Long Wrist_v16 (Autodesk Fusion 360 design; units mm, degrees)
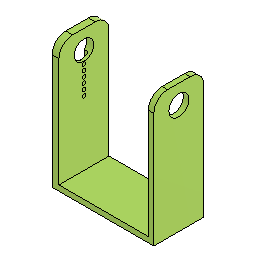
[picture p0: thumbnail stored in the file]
parameter "d10" = 7 (= "( 7 / 2 ) * 1 mm + 1.5 mm + 2 mm")
sketch "Sketch1" plane through (0, 0, 0) normal (0, 0, 1) x axis (1, 0, 0)
  line L1 (-18.6, -9.15) -> (18.6, -9.15)
  line L2 (-18.6, 9.15) -> (-18.6, -9.15)
  line L3 (18.6, 9.15) -> (-18.6, 9.15)
  line L4 (18.6, -9.15) -> (18.6, 9.15)
  line L5 (-18.6, 9.15) -> (18.6, -9.15)
  line L6 (18.6, 9.15) -> (-18.6, -9.15)
  line L7 (16.6, 9.15) -> (18.6, 9.15)
  line L8 (16.6, -9.15) -> (16.6, 9.15)
  line L9 (18.6, -9.15) -> (16.6, -9.15)
  line L10 (18.6, 9.15) -> (18.6, -9.15)
  line L11 (-16.1, 9.15) -> (-18.6, 9.15)
  line L12 (-16.1, -9.15) -> (-16.1, 9.15)
  line L13 (-18.6, -9.15) -> (-16.1, -9.15)
  line L14 (-18.6, 9.15) -> (-18.6, -9.15)
  point P6 (0, 0)
  point P1 (0, 0)
  point P4 (-18.6, 9.15)
  point P5 (18.6, 9.15)
  point P3 (-18.6, -9.15)
  point P7 (16.6, 9.15)
  point P10 (-16.1, 9.15)
  point P11 (-16.1, -9.15)
  point P8 (16.6, -9.15)
  horizontal L1
  perpendicular L1 L2
  parallel L1 L3
  parallel L2 L4
  coincident L5 P6
  coincident L6 P6
  coincident P1 P6
  horizontal L7
  vertical L8
  horizontal L9
  vertical L10
  horizontal L11
  vertical L12
  horizontal L13
  vertical L14
  dimension "d1" distance P4 P5 = 37.2 (= "35.5 mm + 2 mm - 0.3 mm")
  dimension "d2" distance P3 P4 = 18.3
  dimension "d3" distance P5 P7 = 2
  dimension "d4" distance P4 P10 = 2.5
  dimension "d52" distance P10 P11 = 18.3 (= "d2")
  dimension "d53" distance P7 P8 = 18.3 (= "d2")
extrude "Extrude1" new body sketch "Sketch1" profile of L1 L3 L8 L12 along normal blind 2
extrude "Extrude2" add sketch "Sketch1" profile of L1 L3 L4 L7 L8 L9 L10 along normal blind 47
sketch "Sketch2" plane through (18.6, 0, 0) normal (1, 0, 0) x axis (0, 1, 0)
  line L1 (9.15, 0) -> (-9.15, 0)
  line L2 (9.15, 47) -> (9.15, 0)
  line L3 (-9.15, 47) -> (9.15, 47)
  line L4 (-9.15, 0) -> (-9.15, 47)
  circle C1 centre (0, 40) radius 3.65
  dimension "d9" diameter C1 = 7.3
extrude "Extrude3" cut sketch "Sketch2" profile of C1 against normal blind 2
extrude "Extrude4" add sketch "Sketch1" profile of L1 L2 L3 L11 L12 L13 L14 along normal blind 47 (= "2 mm + 25 mm + 20 mm")
fillet "Fillet1" radius 5
sketch "Sketch3" plane through (-18.6, 0, 0) normal (-1, 0, 0) x axis (0, -1, 0)
  line L1 (9.15, 0) -> (-9.15, 0)
  line L2 (9.15, 47) -> (9.15, 0)
  line L3 (-9.15, 47) -> (9.15, 47)
  line L4 (-9.15, 0) -> (-9.15, 47)
  line L5 (-1.997, 25.9409) -> (-2.6411, 37.7278)
  line L6 (2.6411, 37.7278) -> (1.997, 25.9409)
  line L7 (0, 47) -> (0, 0)
  line L8 (-9.15, 40.1) -> (9.15, 40.1)
  circle C1 centre (0, 31.65) radius 0.65
  circle C2 centre (0, 40.1) radius 2.3
  circle C3 centre (0, 27.65) radius 0.65
  arc A1 centre (0, 26.05) radius 2 clockwise from (1.997, 25.9409) to (-1.997, 25.9409)
  circle C4 centre (0, 25.65) radius 0.65
  circle C5 centre (0, 29.65) radius 0.65
  circle C6 centre (0, 35.65) radius 0.65
  circle C7 centre (0, 33.65) radius 0.65
  circle C8 centre (0, 40.1) radius 3.55
  point P1 (0, 0)
  point P17 (0, 0)
  point P18 (0, 47)
  point P19 (9.15, 40.1)
  point P20 (-9.15, 40.1)
  point P23 (2.6411, 37.7278)
  point P24 (-2.6411, 37.7278)
  coincident P1 P17
  midpoint L3 P18
  coincident L2 P19
  coincident L4 P20
  perpendicular L4 L8
  concentric C2 C8
  coincident C8 P23
  coincident C8 P24
  dimension "d19" distance L3 L8 = 6.9 (= "1.45 mm + ( 6.9 / 2 ) * 1 mm + 2 mm")
  dimension "d26" diameter C8 = 7.1
  dimension "d54" diameter C6 = 1.3
  dimension "d55" diameter C7 = 1.3 (= "d54")
  dimension "d56" diameter C1 = 1.3 (= "d54")
  dimension "d57" diameter C5 = 1.3 (= "d54")
  dimension "d58" diameter C3 = 1.3 (= "d54")
  dimension "d59" diameter C4 = 1.3 (= "d54")
extrude "Extrude5" cut sketch "Sketch3" profile of L5 C1 L6 C3 A1 C4 C5 C6 C7 C8 against normal blind 1.4
extrude "Extrude8" cut sketch "Sketch3" profile of C1 C2 C3 C4 C5 C6 C7 C8 against normal blind 2.5
fillet "Fillet2" radius 5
